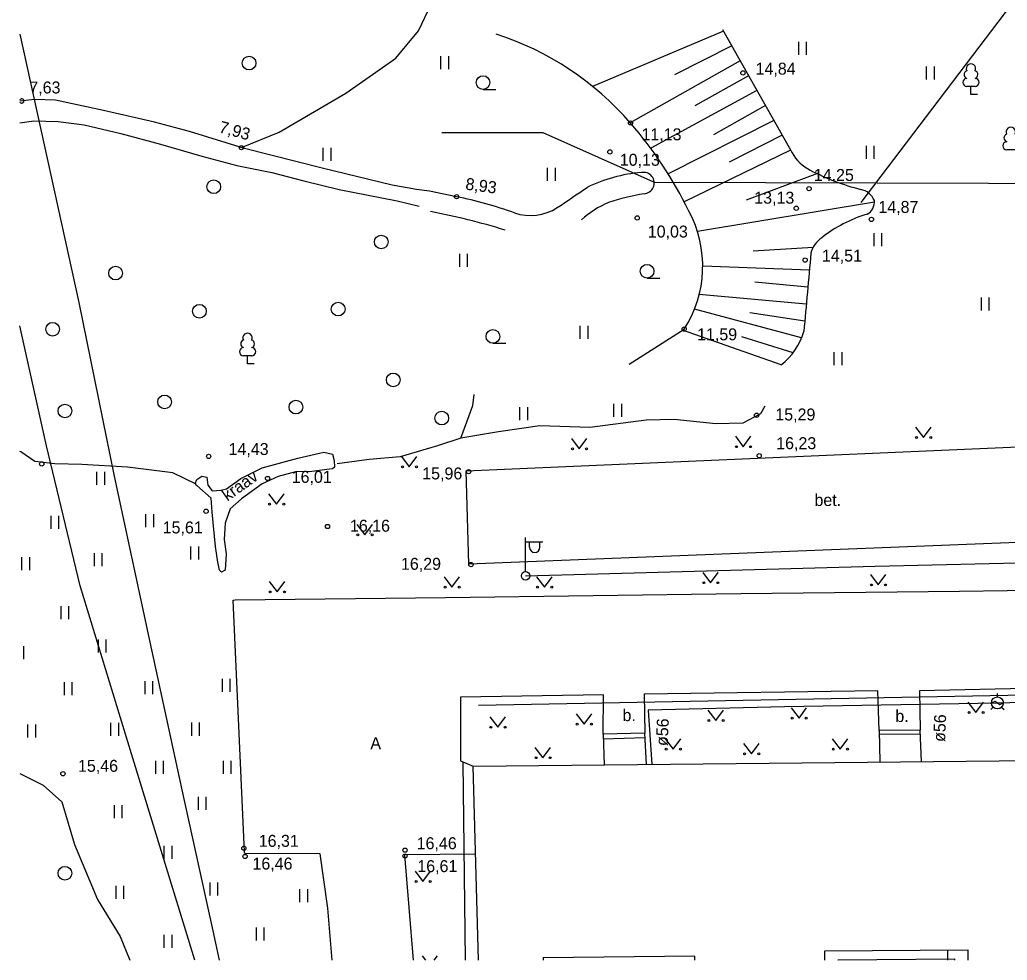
# Model space of a CAD drawing. Extents: x 713540 to 713867, y 6589774 to 6590061.
# Drawn here: x 713540 to 713597.8, y 6589774.1 to 6589829.1 of the extents above; entities that cross this region are included whole.
import ezdxf

# ---------------------------------------------------------------- set-up
doc = ezdxf.new("R2010")
doc.units = 0
for name, color, linetype in [('HALJASTUS', 7, 'Continuous'), ('HOONE', 7, 'Continuous'), ('HOONEDET', 7, 'Continuous'), ('KORGUS', 7, 'Continuous'), ('KTRASS', 7, 'Continuous'), ('MPKAABEL', 7, 'Continuous'), ('POST', 7, 'Continuous'), ('PUU', 7, 'Continuous'), ('RAJATIS', 7, 'Continuous'), ('RELJEEF', 7, 'Continuous'), ('SITRASS', 7, 'Continuous'), ('SKTRASS', 7, 'Continuous'), ('TEE', 7, 'Continuous'), ('TORU NR', 7, 'Continuous'), ('VEEKOGU', 7, 'Continuous')]:
    doc.layers.add(name, color=color, linetype=linetype)

msp = doc.modelspace()

# ---------------------------------------------------------------- linework, layer by layer
at = {"layer": 'HALJASTUS'}
for p, q in [((713585.54, 6589827.817), (713585.54, 6589827.056)), ((713585.995, 6589827.817), (713585.995, 6589827.056)), ((713564.595, 6589826.965), (713564.595, 6589826.204)), ((713565.05, 6589826.965), (713565.05, 6589826.204)), ((713593.018, 6589826.369), (713593.018, 6589825.608)), ((713593.473, 6589826.369), (713593.473, 6589825.608)), ((713567.078, 6589825.029), (713567.828, 6589825.029)), ((713557.712, 6589821.611), (713557.712, 6589820.849)), ((713558.168, 6589821.611), (713558.168, 6589820.849)), ((713589.497, 6589821.725), (713589.497, 6589820.964)), ((713589.952, 6589821.725), (713589.952, 6589820.964)), ((713570.841, 6589820.433), (713570.841, 6589819.672)), ((713571.296, 6589820.433), (713571.296, 6589819.672)), ((713589.943, 6589816.609), (713589.943, 6589815.848)), ((713590.398, 6589816.609), (713590.398, 6589815.848)), ((713565.694, 6589815.404), (713565.694, 6589814.642)), ((713566.149, 6589815.404), (713566.149, 6589814.642)), ((713576.679, 6589813.987), (713577.429, 6589813.987)), ((713596.229, 6589812.846), (713596.229, 6589812.084)), ((713596.684, 6589812.846), (713596.684, 6589812.084)), ((713572.75, 6589811.184), (713572.75, 6589810.422)), ((713573.205, 6589811.184), (713573.205, 6589810.422)), ((713567.656, 6589810.172), (713568.406, 6589810.172)), ((713587.614, 6589809.656), (713587.614, 6589808.895)), ((713588.069, 6589809.656), (713588.069, 6589808.895)), ((713574.722, 6589806.631), (713574.722, 6589805.869)), ((713575.178, 6589806.631), (713575.178, 6589805.869)), ((713569.222, 6589806.431), (713569.222, 6589805.669)), ((713569.678, 6589806.431), (713569.678, 6589805.669)), ((713592.387, 6589805.267), (713592.85, 6589804.66)), ((713592.85, 6589804.66), (713593.296, 6589805.267)), ((713572.247, 6589804.597), (713572.71, 6589803.99)), ((713572.71, 6589803.99), (713573.156, 6589804.597)), ((713581.847, 6589804.727), (713582.31, 6589804.12)), ((713582.31, 6589804.12), (713582.756, 6589804.727)), ((713562.297, 6589803.547), (713562.76, 6589802.94)), ((713562.76, 6589802.94), (713563.206, 6589803.547)), ((713544.462, 6589802.651), (713544.462, 6589801.889)), ((713544.918, 6589802.651), (713544.918, 6589801.889)), ((713554.527, 6589801.367), (713554.99, 6589800.76)), ((713554.99, 6589800.76), (713555.436, 6589801.367)), ((713541.782, 6589800.081), (713541.782, 6589799.319)), ((713542.238, 6589800.081), (713542.238, 6589799.319)), ((713547.332, 6589800.181), (713547.332, 6589799.419)), ((713547.788, 6589800.181), (713547.788, 6589799.419)), ((713559.695, 6589799.574), (713560.158, 6589798.967)), ((713560.158, 6589798.967), (713560.604, 6589799.574)), ((713549.962, 6589798.281), (713549.962, 6589797.519)), ((713550.418, 6589798.281), (713550.418, 6589797.519)), ((713540.072, 6589797.651), (713540.072, 6589796.889)), ((713540.528, 6589797.651), (713540.528, 6589796.889)), ((713544.312, 6589797.891), (713544.312, 6589797.129)), ((713544.768, 6589797.891), (713544.768, 6589797.129)), ((713579.937, 6589796.767), (713580.4, 6589796.16)), ((713580.4, 6589796.16), (713580.846, 6589796.767)), ((713554.567, 6589796.227), (713555.03, 6589795.62)), ((713555.03, 6589795.62), (713555.476, 6589796.227)), ((713564.797, 6589796.507), (713565.26, 6589795.9)), ((713565.26, 6589795.9), (713565.706, 6589796.507)), ((713570.207, 6589796.507), (713570.67, 6589795.9)), ((713570.67, 6589795.9), (713571.116, 6589796.507)), ((713589.747, 6589796.637), (713590.21, 6589796.03)), ((713590.21, 6589796.03), (713590.656, 6589796.637)), ((713542.362, 6589794.781), (713542.362, 6589794.019)), ((713542.818, 6589794.781), (713542.818, 6589794.019)), ((713544.552, 6589792.831), (713544.552, 6589792.069)), ((713545.008, 6589792.831), (713545.008, 6589792.069)), ((713540.188, 6589792.441), (713540.188, 6589791.679)), ((713547.282, 6589790.391), (713547.282, 6589789.629)), ((713547.738, 6589790.391), (713547.738, 6589789.629)), ((713551.812, 6589790.541), (713551.812, 6589789.779)), ((713552.268, 6589790.541), (713552.268, 6589789.779)), ((713542.562, 6589790.341), (713542.562, 6589789.579)), ((713543.018, 6589790.341), (713543.018, 6589789.579)), ((713580.237, 6589788.707), (713580.7, 6589788.1)), ((713580.7, 6589788.1), (713581.146, 6589788.707)), ((713585.107, 6589788.847), (713585.57, 6589788.24)), ((713585.57, 6589788.24), (713586.016, 6589788.847)), ((713595.457, 6589789.167), (713595.92, 6589788.56)), ((713595.92, 6589788.56), (713596.366, 6589789.167)), ((713567.477, 6589788.307), (713567.94, 6589787.7)), ((713567.94, 6589787.7), (713568.386, 6589788.307)), ((713572.527, 6589788.487), (713572.99, 6589787.88)), ((713572.99, 6589787.88), (713573.436, 6589788.487)), ((713540.422, 6589787.861), (713540.422, 6589787.099)), ((713540.878, 6589787.861), (713540.878, 6589787.099)), ((713545.282, 6589787.961), (713545.282, 6589787.199)), ((713545.738, 6589787.961), (713545.738, 6589787.199)), ((713550.012, 6589787.971), (713550.012, 6589787.209)), ((713550.468, 6589787.971), (713550.468, 6589787.209)), ((713577.737, 6589787.027), (713578.2, 6589786.42)), ((713578.2, 6589786.42), (713578.646, 6589787.027)), ((713587.517, 6589787.027), (713587.98, 6589786.42)), ((713587.98, 6589786.42), (713588.426, 6589787.027)), ((713570.117, 6589786.527), (713570.58, 6589785.92)), ((713570.58, 6589785.92), (713571.026, 6589786.527)), ((713582.327, 6589786.757), (713582.79, 6589786.15)), ((713582.79, 6589786.15), (713583.236, 6589786.757)), ((713547.912, 6589785.731), (713547.912, 6589784.969)), ((713548.368, 6589785.731), (713548.368, 6589784.969)), ((713551.862, 6589785.731), (713551.862, 6589784.969)), ((713552.318, 6589785.731), (713552.318, 6589784.969)), ((713550.402, 6589783.631), (713550.402, 6589782.869)), ((713550.858, 6589783.631), (713550.858, 6589782.869)), ((713545.482, 6589783.141), (713545.482, 6589782.379)), ((713545.938, 6589783.141), (713545.938, 6589782.379)), ((713548.402, 6589780.761), (713548.402, 6589779.999)), ((713548.858, 6589780.761), (713548.858, 6589779.999)), ((713563.097, 6589779.287), (713563.56, 6589778.68)), ((713563.56, 6589778.68), (713564.006, 6589779.287)), ((713545.582, 6589778.431), (713545.582, 6589777.669)), ((713546.038, 6589778.431), (713546.038, 6589777.669)), ((713551.082, 6589778.621), (713551.082, 6589777.859)), ((713551.538, 6589778.621), (713551.538, 6589777.859)), ((713556.342, 6589778.231), (713556.342, 6589777.469)), ((713556.798, 6589778.231), (713556.798, 6589777.469)), ((713553.802, 6589775.991), (713553.802, 6589775.229)), ((713554.258, 6589775.991), (713554.258, 6589775.229)), ((713548.402, 6589775.551), (713548.402, 6589774.789)), ((713548.858, 6589775.551), (713548.858, 6589774.789)), ((713563.507, 6589774.327), (713563.704, 6589774.068)), ((713564.226, 6589774.068), (713564.416, 6589774.327))]:
    msp.add_line(p, q, dxfattribs=at)
for points in [[(713552.95, 6589821.62), (713555.14, 6589822.52), (713559.05, 6589824.8), (713561.98, 6589826.85), (713563.31, 6589828.45), (713564.63, 6589831.26), (713566.41, 6589833.52), (713568.19, 6589835.5), (713570.55, 6589838.16), (713571.54, 6589839.75), (713571.8, 6589840.81), (713571.31, 6589841.12), (713567.98, 6589841.64), (713564.71, 6589841.83), (713563.08, 6589841.87), (713559.89, 6589841.53), (713557.65, 6589841.53), (713553.91, 6589841.61), (713551.9, 6589841.99), (713549.01, 6589842.29), (713544.76, 6589842.44), (713542.57, 6589842.1), (713539.99, 6589841.38), (713539.965, 6589841.37)], [(713565.78, 6589804.62), (713566.48, 6589806.53), (713566.557, 6589807.174)], [(713583.562, 6589806.484), (713583.31, 6589806.05), (713582.28, 6589805.5), (713580.7, 6589805.46), (713578.27, 6589805.72), (713576.62, 6589805.68), (713573.32, 6589805.24), (713570.41, 6589805.35), (713567.99, 6589804.98), (713565.78, 6589804.62)], [(713565.78, 6589804.62), (713564.42, 6589804.18), (713562.22, 6589803.52), (713560.42, 6589803.37), (713558.54, 6589803.11)], [(713550.29, 6589801.93), (713548.93, 6589802.6), (713546.28, 6589802.93), (713543.6, 6589803.07), (713542.02, 6589803.11), (713540.84, 6589803.26), (713540.03, 6589803.81), (713539.965, 6589803.847)], [(713621.54, 6589790), (713566.82, 6589788.98)], [(713539.965, 6589784.989), (713541.33, 6589784.32), (713542.43, 6589783.33), (713543.16, 6589780.84), (713544.52, 6589777.62), (713545.84, 6589775.46), (713546.405, 6589774.068)]]:
    msp.add_lwpolyline(points, dxfattribs=at)
for centre, radius in [((713553.39, 6589826.57), 0.4), ((713567.078, 6589825.429), 0.4), ((713551.32, 6589819.33), 0.4), ((713561.12, 6589816.1), 0.4), ((713545.57, 6589814.28), 0.4), ((713576.679, 6589814.387), 0.4), ((713550.48, 6589812.05), 0.4), ((713558.6, 6589812.17), 0.4), ((713541.89, 6589810.99), 0.4), ((713567.656, 6589810.572), 0.4), ((713561.82, 6589808.03), 0.4), ((713542.61, 6589806.21), 0.4), ((713548.44, 6589806.74), 0.4), ((713556.13, 6589806.44), 0.4), ((713564.66, 6589805.79), 0.4), ((713592.449, 6589804.66), 0.055), ((713593.278, 6589804.66), 0.055), ((713572.309, 6589803.99), 0.055), ((713573.138, 6589803.99), 0.055), ((713581.909, 6589804.12), 0.055), ((713582.738, 6589804.12), 0.055), ((713562.359, 6589802.94), 0.055), ((713563.188, 6589802.94), 0.055), ((713554.589, 6589800.76), 0.055), ((713555.418, 6589800.76), 0.055), ((713559.757, 6589798.967), 0.055), ((713560.586, 6589798.967), 0.055), ((713579.999, 6589796.16), 0.055), ((713580.828, 6589796.16), 0.055), ((713554.629, 6589795.62), 0.055), ((713555.458, 6589795.62), 0.055), ((713564.859, 6589795.9), 0.055), ((713565.688, 6589795.9), 0.055), ((713570.269, 6589795.9), 0.055), ((713571.098, 6589795.9), 0.055), ((713589.809, 6589796.03), 0.055), ((713590.638, 6589796.03), 0.055), ((713580.299, 6589788.1), 0.055), ((713581.128, 6589788.1), 0.055), ((713585.169, 6589788.24), 0.055), ((713585.998, 6589788.24), 0.055), ((713595.519, 6589788.56), 0.055), ((713596.348, 6589788.56), 0.055), ((713567.539, 6589787.7), 0.055), ((713568.368, 6589787.7), 0.055), ((713572.589, 6589787.88), 0.055), ((713573.418, 6589787.88), 0.055), ((713577.799, 6589786.42), 0.055), ((713578.628, 6589786.42), 0.055), ((713587.579, 6589786.42), 0.055), ((713588.408, 6589786.42), 0.055), ((713570.179, 6589785.92), 0.055), ((713571.008, 6589785.92), 0.055), ((713582.389, 6589786.15), 0.055), ((713583.218, 6589786.15), 0.055), ((713542.61, 6589779.16), 0.4), ((713563.159, 6589778.68), 0.055), ((713563.988, 6589778.68), 0.055)]:
    msp.add_circle(centre, radius, dxfattribs=at)
at = {"layer": 'HOONE'}
for p, q in [((713596.83, 6589789.128), (713597.041, 6589789.234)), ((713597.041, 6589789.234), (713597.319, 6589789.026)), ((713597.18, 6589789.48), (713597.18, 6589789.677)), ((713596.933, 6589788.883), (713596.793, 6589788.743)), ((713597.319, 6589789.026), (713597.53, 6589789.132)), ((713597.427, 6589788.883), (713597.567, 6589788.743))]:
    msp.add_line(p, q, dxfattribs=at)
for points in [[(713589.21, 6589818.4), (713598.395, 6589830.514), (713600.619, 6589833.447), (713601.88, 6589835.11), (713609.6, 6589852.68), (713621.203, 6589880.532)], [(713597.18, 6589789.12), (713584.73, 6589788.9), (713576.75, 6589788.71), (713576.96, 6589785.53)], [(713599.38, 6589789.17), (713597.18, 6589789.12)], [(713566.805, 6589774.068), (713566.5, 6589785.43), (713631.91, 6589786.08), (713631.916, 6589784.338)], [(713579.468, 6589774.068), (713579.466, 6589774.316), (713570.59, 6589774.216), (713570.603, 6589774.068)], [(713595.479, 6589774.068), (713595.475, 6589774.659), (713587.063, 6589774.596), (713587.067, 6589774.068)]]:
    msp.add_lwpolyline(points, dxfattribs=at)
msp.add_circle((713597.18, 6589789.13), 0.35, dxfattribs=at)
at = {"layer": 'HOONEDET'}
for points in [[(713592.73, 6589785.69), (713592.67, 6589787.54), (713590.26, 6589787.52), (713590.3, 6589785.67)], [(713576.64, 6589785.53), (713576.55, 6589787.36), (713574.1, 6589787.29), (713574.17, 6589785.51)], [(713576.56, 6589787.09), (713574.11, 6589787.01)], [(713592.68, 6589787.29), (713590.27, 6589787.28)]]:
    msp.add_lwpolyline(points, dxfattribs=at)
at = {"layer": 'KORGUS'}
for centre in [(713582.29, 6589825.99), (713575.71, 6589823.06), (713552.94, 6589821.62), (713574.5, 6589821.37), (713586.16, 6589819.22), (713565.53, 6589818.75), (713585.41, 6589818.07), (713576.1, 6589817.51), (713589.81, 6589817.42), (713585.93, 6589815.04), (713578.85, 6589811), (713583.09, 6589805.96), (713551.02, 6589803.55), (713583.24, 6589803.59), (713541.25, 6589803.11), (713566.23, 6589802.66), (713554.47, 6589802.26), (713550.87, 6589800.34), (713557.98, 6589799.45), (713566.37, 6589797.22), (713542.49, 6589784.98), (713553.08, 6589780.62), (713562.51, 6589780.51), (713553.15, 6589780.14), (713562.51, 6589780.17)]:
    msp.add_circle(centre, 0.125, dxfattribs=at)
msp.add_arc((713540.08, 6589824.35), 0.125, 203.19756, 156.80244, dxfattribs=at)
at = {"layer": 'KTRASS'}
msp.add_lwpolyline([(713594.279, 6589774.068), (713594.274, 6589774.65)], dxfattribs=at)
at = {"layer": 'MPKAABEL'}
msp.add_lwpolyline([(713569.57, 6589796.56), (713590.03, 6589797.12), (713600.03, 6589797.36)], dxfattribs=at)
at = {"layer": 'POST'}
for p, q in [((713569.57, 6589796.81), (713569.57, 6589798.81)), ((713569.57, 6589798.56), (713570.57, 6589798.56)), ((713569.797, 6589798.239), (713569.797, 6589798.56)), ((713570.409, 6589798.239), (713570.409, 6589798.56))]:
    msp.add_line(p, q, dxfattribs=at)
msp.add_circle((713569.57, 6589796.56), 0.25, dxfattribs=at)
msp.add_arc((713570.103, 6589798.239), 0.306, 180, 0, dxfattribs=at)
at = {"layer": 'PUU'}
for p, q in [((713595.874, 6589825.199), (713595.394, 6589825.199)), ((713595.634, 6589824.724), (713595.634, 6589825.199)), ((713596.014, 6589824.724), (713595.634, 6589824.724)), ((713598.207, 6589821.492), (713597.727, 6589821.492)), ((713553.54, 6589809.445), (713553.06, 6589809.445)), ((713553.3, 6589808.97), (713553.3, 6589809.445)), ((713553.68, 6589808.97), (713553.3, 6589808.97))]:
    msp.add_line(p, q, dxfattribs=at)
for centre, radius, start, end in [((713595.634, 6589826.244), 0.277, 332.5799, 207.4201), ((713595.396, 6589825.437), 0.238, 90.0016, 269.3953), ((713595.464, 6589825.897), 0.233, 109.02174, 253.14154), ((713595.804, 6589825.897), 0.233, 286.85082, 70.98591), ((713595.871, 6589825.437), 0.238, 270.6047, 89.9984), ((713597.967, 6589822.537), 0.277, 332.5799, 207.4201), ((713597.797, 6589822.189), 0.233, 109.02174, 253.14154), ((713597.729, 6589821.729), 0.238, 90.0016, 269.3953), ((713553.3, 6589810.49), 0.277, 332.5799, 207.4201), ((713553.13, 6589810.143), 0.233, 109.02174, 253.14154), ((713553.47, 6589810.143), 0.233, 286.85082, 70.98591), ((713553.063, 6589809.682), 0.238, 90.0016, 269.3953), ((713553.537, 6589809.682), 0.238, 270.6047, 89.9984)]:
    msp.add_arc(centre, radius, start, end, dxfattribs=at)
at = {"layer": 'RAJATIS'}
msp.add_lwpolyline([(713577.074, 6589819.597), (713570.605, 6589822.48), (713564.664, 6589822.48)], dxfattribs=at)
at = {"layer": 'RELJEEF'}
for p, q in [((713581.145, 6589828.439), (713573.494, 6589825.199)), ((713581.636, 6589827.568), (713578.284, 6589825.871)), ((713582.127, 6589826.697), (713575.698, 6589823.073)), ((713582.618, 6589825.826), (713579.483, 6589824.058)), ((713583.109, 6589824.955), (713576.898, 6589821.58)), ((713583.6, 6589824.084), (713580.568, 6589822.374)), ((713584.091, 6589823.213), (713577.911, 6589820.09)), ((713584.582, 6589822.341), (713581.487, 6589820.775)), ((713585.073, 6589821.47), (713578.85, 6589818.445)), ((713586.643, 6589820.097), (713582.475, 6589818.538)), ((713589.985, 6589818.435), (713579.622, 6589816.721)), ((713586.398, 6589815.784), (713582.895, 6589815.57)), ((713586.177, 6589814.452), (713579.936, 6589814.675)), ((713586.086, 6589813.456), (713582.988, 6589813.74)), ((713585.995, 6589812.46), (713579.719, 6589813.033)), ((713585.721, 6589810.488), (713579.453, 6589812.168)), ((713585.904, 6589811.464), (713582.689, 6589811.954)), ((713584.534, 6589808.907), (713578.753, 6589810.938)), ((713585.231, 6589809.62), (713582.223, 6589810.557))]:
    msp.add_line(p, q, dxfattribs=at)
for points in [[(713581.096, 6589828.525), (713585.163, 6589821.312)], [(713575.621, 6589808.949), (713578.85, 6589811)]]:
    msp.add_lwpolyline(points, dxfattribs=at)
for centre, radius, start, end in [((713562.397, 6589811.489), 17.639, 40.99608, 71.99266), ((713558.013, 6589807.642), 23.471, 25.91382, 41.063), ((713587.321, 6589822.528), 2.477, 209.41094, 243.89119), ((713592.513, 6589832.347), 13.584, 242.4517, 255.81236), ((713588.929, 6589818.05), 1.156, 24.56906, 77.2858), ((713589.18, 6589818.443), 0.806, 297.53987, 6.24928), ((713573.151, 6589814.682), 6.784, 327.13538, 28.31292), ((713592.029, 6589809.738), 8.366, 107.22562, 127.81931), ((713587.774, 6589815.062), 1.554, 124.22983, 165.6708), ((718829.085, 6589333.491), 5264.922, 174.747737, 174.797866), ((713582.162, 6589811.924), 3.838, 308.17716, 343.89736)]:
    msp.add_arc(centre, radius, start, end, dxfattribs=at)
at = {"layer": 'SITRASS'}
for points in [[(713539.965, 6589828.251), (713543.43, 6589812.55)], [(713543.43, 6589812.55), (713545.49, 6589802.39), (713547.52, 6589792.95), (713549.45, 6589784.05), (713551.27, 6589775.78), (713551.63, 6589774.068)], [(713550.211, 6589774.068), (713546.51, 6589786.15), (713543.51, 6589795.97), (713541.54, 6589804.17), (713539.965, 6589811.197)]]:
    msp.add_lwpolyline(points, dxfattribs=at)
at = {"layer": 'SKTRASS'}
msp.add_lwpolyline([(713577.074, 6589819.597), (713648.925, 6589819.388)], dxfattribs=at)
at = {"layer": 'TEE'}
for points in [[(713558.242, 6589774.068), (713558, 6589777.11), (713557.55, 6589780.29), (713553.14, 6589780.32), (713553.11, 6589780.41), (713552.46, 6589795.14), (713552.58, 6589795.15), (713564.88, 6589795.29), (713582.17, 6589795.52), (713594.953, 6589795.665), (713611.695, 6589795.898), (713616.978, 6589806.321), (713631.194, 6589806.435), (713655.999, 6589806.607), (713675.755, 6589806.635), (713680.518, 6589806.639), (713701.336, 6589806.867)], [(713566.1, 6589802.7), (713606.93, 6589804.48), (713607.23, 6589798.86), (713566.25, 6589797.24), (713566.1, 6589802.7)], [(713590.26, 6589787.52), (713590.19, 6589789.84), (713576.5, 6589789.64), (713576.55, 6589787.36)], [(713606, 6589787.58), (713605.93, 6589790.13), (713592.62, 6589789.84), (713592.67, 6589787.54)], [(713574.1, 6589787.29), (713574.12, 6589789.59), (713565.76, 6589789.46), (713565.76, 6589785.74), (713566.5, 6589785.43)], [(713565.902, 6589785.635), (713566.042, 6589774.068)], [(713566.64, 6589780.28), (713562.48, 6589780.23), (713562.994, 6589774.068)], [(713587.867, 6589774.068), (713587.867, 6589774.102), (713594.679, 6589774.153), (713594.679, 6589774.068)]]:
    msp.add_lwpolyline(points, dxfattribs=at)
at = {"layer": 'VEEKOGU'}
for points in [[(713565.53, 6589818.75), (713563.943, 6589819.078), (713563.177, 6589819.171), (713561.76, 6589819.43), (713557.66, 6589820.42), (713553.11, 6589821.57), (713549.89, 6589822.56), (713547.85, 6589823.11), (713544.86, 6589823.8), (713542.06, 6589824.39), (713540.82, 6589824.43), (713539.965, 6589824.337)], [(713565.53, 6589818.75), (713563.943, 6589819.078), (713563.177, 6589819.171), (713561.76, 6589819.43), (713557.66, 6589820.42), (713553.11, 6589821.57), (713549.89, 6589822.56), (713547.85, 6589823.11), (713544.86, 6589823.8), (713542.06, 6589824.39), (713540.82, 6589824.43), (713539.965, 6589824.337)], [(713539.965, 6589823.062), (713540.79, 6589823.19), (713542.22, 6589823.15), (713543.74, 6589822.96), (713545.88, 6589822.44), (713548.21, 6589821.83), (713550.63, 6589821.12), (713552.67, 6589820.57), (713554.71, 6589820.17), (713556.6, 6589819.67), (713558.66, 6589819.17), (713562.05, 6589818.5), (713563.35, 6589818.194)], [(713550.32, 6589801.85), (713550.23, 6589801.97), (713550.32, 6589802.2), (713550.63, 6589802.4), (713550.91, 6589802.33), (713550.97, 6589801.87), (713551.23, 6589801.53), (713551.73, 6589801.57), (713552.07, 6589801.65), (713552.9, 6589802.25), (713554.15, 6589802.88), (713556.24, 6589803.45), (713557.77, 6589803.79), (713558.27, 6589803.69), (713558.36, 6589803.32), (713558.38, 6589802.92), (713558.27, 6589802.82), (713557.93, 6589802.78), (713556.92, 6589802.65), (713556.18, 6589802.67), (713555.08, 6589802.37), (713554.15, 6589801.95), (713552.94, 6589801.06), (713552.28, 6589800.49), (713551.99, 6589799.64), (713551.92, 6589798.69), (713552.05, 6589797.85), (713551.99, 6589796.9), (713551.78, 6589796.77), (713551.65, 6589796.9), (713551.56, 6589797.36), (713551.42, 6589798.27), (713551.23, 6589800.28), (713551.16, 6589801.1), (713550.32, 6589801.85)]]:
    msp.add_lwpolyline(points, dxfattribs=at)
for centre, radius, start, end in [((713577.035, 6589811.45), 8.74, 94.52677, 116.24702), ((713576.466, 6589819.547), 0.628, 273.49438, 101.11581), ((713381.901, 6590102.333), 341.61, 303.69639, 304.04908), ((713560.255, 6589793.267), 26.023, 70.54616, 78.30532), ((713578.583, 6589806.085), 13.002, 99.20056, 108.67246), ((713576.504, 6589813.391), 5.428, 112.57256, 132.58462), ((713556.749, 6589779.499), 39.062, 72.6967, 79.30611), ((713569.861, 6589820.461), 2.818, 250.54616, 303.69639)]:
    msp.add_arc(centre, radius, start, end, dxfattribs=at)

# ---------------------------------------------------------------- texts
at = {"layer": 'KORGUS'}
for s, p in [('14,84', (713583.029, 6589825.89)), ('7,63', (713540.526, 6589824.79)), ('11,13', (713576.351, 6589822.05)), ('10,13', (713575.081, 6589820.56)), ('14,25', (713586.436, 6589819.67)), ('13,13', (713582.951, 6589818.34)), ('14,87', (713590.216, 6589817.8)), ('10,03', (713576.721, 6589816.36)), ('14,51', (713586.912, 6589814.95)), ('11,59', (713579.606, 6589810.345)), ('15,29', (713584.186, 6589805.655)), ('14,43', (713552.186, 6589803.635)), ('16,23', (713584.236, 6589803.975)), ('16,01', (713555.882, 6589802.005)), ('15,96', (713563.52, 6589802.205)), ('15,61', (713548.332, 6589799.045)), ('16,16', (713559.29, 6589799.145)), ('16,29', (713562.276, 6589796.915)), ('15,46', (713543.375, 6589785.095)), ('16,31', (713553.952, 6589780.705)), ('16,46', (713563.195, 6589780.565)), ('16,46', (713553.585, 6589779.375)), ('16,61', (713563.232, 6589779.225))]:
    msp.add_text(s, height=0.7, dxfattribs=at).set_placement(p)
for s, rotation, p in [('7,93', 344.83367, (713551.578, 6589822.521)), ('8,93', 352.45212, (713566.018, 6589819.168))]:
    msp.add_text(s, height=0.7, rotation=rotation, dxfattribs=at).set_placement(p)
at = {"layer": 'TEE'}
for s, p in [('bet.', (713586.474, 6589800.65)), ('b.', (713575.239, 6589788.06)), ('b.', (713591.209, 6589788.01)), ('A', (713560.484, 6589786.42))]:
    msp.add_text(s, height=0.7, dxfattribs=at).set_placement(p)
at = {"layer": 'TORU NR'}
for p in [(713577.888, 6589786.594), (713594.118, 6589786.834)]:
    msp.add_text('ø56', height=0.7, rotation=87.68626, dxfattribs=at).set_placement(p)
at = {"layer": 'VEEKOGU'}
msp.add_text('kraav', height=0.7, rotation=35.50462, dxfattribs=at).set_placement((713552.12, 6589800.901))

doc.saveas('drawing.dxf')
